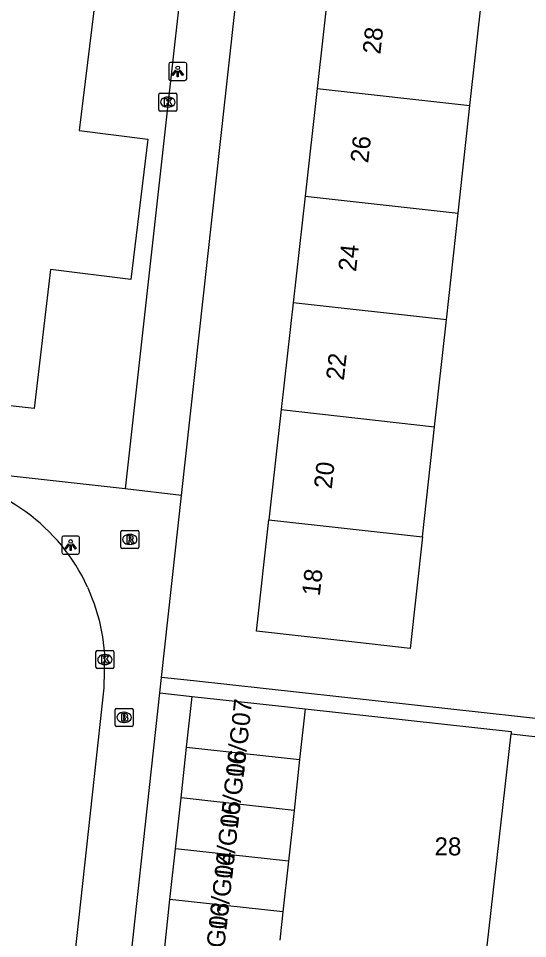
# Model space of a CAD drawing. Extents: x 161928 to 163055, y 386475 to 387428.
# Drawn here: x 162177.9 to 162206.2, y 387064.4 to 387115.4 of the extents above; entities that cross this region are included whole.
import ezdxf

# ---------------------------------------------------------------- set-up
doc = ezdxf.new("R2010")
doc.units = 0
for name, color, linetype in [('IMGEO_Brandkraan', 7, 'Continuous'), ('IMGEO_Groenvoorziening', 7, 'Continuous'), ('IMGEO_Kolk', 7, 'Continuous'), ('IMGEO_Lichtpunt', 7, 'Continuous'), ('IMGEO_Pand', 7, 'Continuous'), ('IMGEO_Pand_nummerreeks', 7, 'Continuous'), ('IMGEO_Rijbaan_lokaal_open', 7, 'Continuous'), ('IMGEO_Rioolput', 7, 'Continuous'), ('IMGEO_Voetpad_open', 7, 'Continuous')]:
    doc.layers.add(name, color=color, linetype=linetype)

msp = doc.modelspace()

# ---------------------------------------------------------------- linework, layer by layer
at = {"layer": 'IMGEO_Brandkraan'}
for p, q in [((162183.308, 387076.214), (162183.308, 387077.066)), ((162183.383, 387077.14), (162184.235, 387077.14)), ((162183.796, 387076.92), (162183.821, 387076.92)), ((162184.309, 387077.066), (162184.309, 387076.214)), ((162183.819, 387076.36), (162183.794, 387076.36)), ((162184.235, 387076.14), (162183.383, 387076.14))]:
    msp.add_line(p, q, dxfattribs=at)
for points in [[(162183.308, 387076.214), (162183.308, 387077.066)], [(162183.383, 387077.14), (162184.235, 387077.14)], [(162183.656, 387076.84), (162183.656, 387076.44), (162183.869, 387076.44)], [(162183.887, 387076.84), (162183.656, 387076.84)], [(162183.835, 387076.759), (162183.781, 387076.759), (162183.781, 387076.683)], [(162184.309, 387077.066), (162184.309, 387076.214)], [(162183.781, 387076.683), (162183.834, 387076.683)], [(162183.843, 387076.607), (162183.781, 387076.607), (162183.781, 387076.526)], [(162183.781, 387076.526), (162183.843, 387076.526)], [(162184.235, 387076.14), (162183.383, 387076.14)]]:
    msp.add_lwpolyline(points, dxfattribs=at)
for centre, radius, start, end in [((162183.385, 387077.064), 0.0765, 91.552, 178.448), ((162183.385, 387077.064), 0.0765, 91.552, 178.448), ((162183.836, 387076.721), 0.0379, 267.8285, 90.9355), ((162183.891, 387076.695), 0.145, 59.4692, 91.5367), ((162183.916, 387076.742), 0.0922, 285.5137, 58.1501), ((162184.233, 387077.064), 0.0765, 1.552, 88.448), ((162184.233, 387077.064), 0.0765, 1.552, 88.448), ((162183.844, 387076.566), 0.0404, 269.8759, 90.5077), ((162183.875, 387076.691), 0.251, 268.6676, 293.5347), ((162183.921, 387076.55), 0.105, 301.3115, 78.989), ((162183.385, 387076.216), 0.0765, 181.552, 268.448), ((162183.385, 387076.216), 0.0765, 181.552, 268.448), ((162184.233, 387076.216), 0.0765, 271.552, 358.448), ((162184.233, 387076.216), 0.0765, 271.552, 358.448)]:
    msp.add_arc(centre, radius, start, end, dxfattribs=at)
for centre, major_axis, ratio, start_param, end_param in [((162183.795, 387076.64), (-0.387, 0.002), 0.722429, 4.712389, 7.853982), ((162183.82, 387076.64), (-0.39, 0.002), 0.717154, 1.570796, 4.712389)]:
    msp.add_ellipse(centre, major_axis=major_axis, ratio=ratio, start_param=start_param, end_param=end_param, dxfattribs=at)
at = {"layer": 'IMGEO_Groenvoorziening'}
msp.add_lwpolyline([(162154.203, 387127.848), (162155.402, 387137.861), (162174.608, 387135.503), (162173.926, 387129.945), (162180.477, 387129.142), (162179.565, 387121.698), (162182.791, 387121.303), (162181.309, 387109.194), (162185.131, 387108.727), (162184.179, 387100.935), (162179.719, 387101.481), (162178.823, 387093.771), (162172.783, 387094.444)], dxfattribs=at)
at = {"layer": 'IMGEO_Kolk'}
for p, q in [((162185.734, 387110.349), (162185.734, 387111.201)), ((162185.809, 387111.275), (162186.661, 387111.275)), ((162186.222, 387111.055), (162186.247, 387111.055)), ((162186.735, 387111.201), (162186.735, 387110.349)), ((162186.245, 387110.495), (162186.22, 387110.495)), ((162186.661, 387110.275), (162185.809, 387110.275)), ((162182.318, 387080.346), (162183.17, 387080.346)), ((162182.243, 387079.42), (162182.243, 387080.272)), ((162182.731, 387080.126), (162182.756, 387080.126)), ((162183.244, 387080.272), (162183.244, 387079.42)), ((162183.17, 387079.346), (162182.318, 387079.346)), ((162182.754, 387079.566), (162182.729, 387079.566))]:
    msp.add_line(p, q, dxfattribs=at)
for points in [[(162185.734, 387110.349), (162185.734, 387111.201)], [(162185.809, 387111.275), (162186.661, 387111.275)], [(162186.055, 387110.975), (162186.178, 387110.975), (162186.178, 387110.824), (162186.308, 387110.975), (162186.472, 387110.975), (162186.326, 387110.824), (162186.479, 387110.575), (162186.327, 387110.575), (162186.242, 387110.739), (162186.178, 387110.672), (162186.178, 387110.575), (162186.055, 387110.575), (162186.055, 387110.975)], [(162186.735, 387111.201), (162186.735, 387110.349)], [(162186.661, 387110.275), (162185.809, 387110.275)], [(162182.318, 387080.346), (162183.17, 387080.346)], [(162182.243, 387079.42), (162182.243, 387080.272)], [(162182.564, 387080.046), (162182.687, 387080.046), (162182.687, 387079.895), (162182.817, 387080.046), (162182.981, 387080.046), (162182.835, 387079.895), (162182.988, 387079.646), (162182.836, 387079.646), (162182.751, 387079.81), (162182.687, 387079.743), (162182.687, 387079.646), (162182.564, 387079.646), (162182.564, 387080.046)], [(162183.244, 387080.272), (162183.244, 387079.42)], [(162183.17, 387079.346), (162182.318, 387079.346)]]:
    msp.add_lwpolyline(points, dxfattribs=at)
for centre, start, end in [((162185.811, 387111.199), 91.552, 178.448), ((162185.811, 387111.199), 91.552, 178.448), ((162186.659, 387111.199), 1.552, 88.448), ((162186.659, 387111.199), 1.552, 88.448), ((162185.811, 387110.351), 181.552, 268.448), ((162185.811, 387110.351), 181.552, 268.448), ((162186.659, 387110.351), 271.552, 358.448), ((162186.659, 387110.351), 271.552, 358.448), ((162182.32, 387080.27), 91.552, 178.448), ((162182.32, 387080.27), 91.552, 178.448), ((162183.168, 387080.27), 1.552, 88.448), ((162183.168, 387080.27), 1.552, 88.448), ((162182.32, 387079.422), 181.552, 268.448), ((162182.32, 387079.422), 181.552, 268.448), ((162183.168, 387079.422), 271.552, 358.448), ((162183.168, 387079.422), 271.552, 358.448)]:
    msp.add_arc(centre, 0.0765, start, end, dxfattribs=at)
for centre, major_axis, ratio, start_param, end_param in [((162186.221, 387110.775), (-0.387, 0.002), 0.722429, 4.712389, 7.853982), ((162186.246, 387110.775), (-0.39, 0.002), 0.717154, 1.570796, 4.712389), ((162182.73, 387079.846), (-0.387, 0.002), 0.722429, 4.712389, 7.853982), ((162182.755, 387079.846), (-0.39, 0.002), 0.717154, 1.570796, 4.712389)]:
    msp.add_ellipse(centre, major_axis=major_axis, ratio=ratio, start_param=start_param, end_param=end_param, dxfattribs=at)
at = {"layer": 'IMGEO_Lichtpunt'}
for p, q in [((162186.286, 387112.881), (162186.286, 387112.074)), ((162186.286, 387112.881), (162186.286, 387112.074)), ((162187.188, 387112.976), (162186.38, 387112.976)), ((162187.188, 387112.976), (162186.38, 387112.976)), ((162187.282, 387112.074), (162187.282, 387112.881)), ((162187.282, 387112.074), (162187.282, 387112.881)), ((162186.38, 387111.98), (162187.188, 387111.98)), ((162186.38, 387111.98), (162187.188, 387111.98)), ((162180.342, 387086.604), (162180.342, 387085.797)), ((162180.342, 387086.604), (162180.342, 387085.797)), ((162181.244, 387086.699), (162180.436, 387086.699)), ((162181.244, 387086.699), (162180.436, 387086.699)), ((162181.338, 387085.797), (162181.338, 387086.604)), ((162181.338, 387085.797), (162181.338, 387086.604)), ((162180.436, 387085.703), (162181.244, 387085.703)), ((162180.436, 387085.703), (162181.244, 387085.703))]:
    msp.add_line(p, q, dxfattribs=at)
for points in [[(162186.66, 387112.545), (162186.699, 387112.517), (162186.511, 387112.255), (162186.473, 387112.282), (162186.66, 387112.545)], [(162186.762, 387112.497), (162186.809, 387112.497), (162186.809, 387112.175), (162186.762, 387112.175), (162186.762, 387112.497)], [(162186.872, 387112.517), (162186.91, 387112.544), (162187.097, 387112.282), (162187.058, 387112.254), (162186.872, 387112.517)], [(162180.716, 387086.268), (162180.755, 387086.24), (162180.567, 387085.978), (162180.529, 387086.005), (162180.716, 387086.268)], [(162180.818, 387086.22), (162180.865, 387086.22), (162180.865, 387085.898), (162180.818, 387085.898), (162180.818, 387086.22)], [(162180.928, 387086.24), (162180.966, 387086.267), (162181.153, 387086.005), (162181.114, 387085.977), (162180.928, 387086.24)]]:
    msp.add_lwpolyline(points, dxfattribs=at)
for centre in [(162186.785, 387112.679), (162180.841, 387086.402)]:
    msp.add_circle(centre, 0.0994, dxfattribs=at)
for centre, start, end in [((162186.38, 387112.881), 90, 180), ((162186.38, 387112.881), 90, 180), ((162187.188, 387112.881), 0, 90), ((162187.188, 387112.881), 0, 90), ((162186.38, 387112.074), 180, 270), ((162186.38, 387112.074), 180, 270), ((162187.188, 387112.074), 270, 0), ((162187.188, 387112.074), 270, 360), ((162180.436, 387086.604), 90, 180), ((162180.436, 387086.604), 90, 180), ((162181.244, 387086.604), 0, 90), ((162181.244, 387086.604), 0, 90), ((162180.436, 387085.797), 180, 270), ((162180.436, 387085.797), 180, 270), ((162181.244, 387085.797), 270, 0), ((162181.244, 387085.797), 270, 360)]:
    msp.add_arc(centre, 0.0946, start, end, dxfattribs=at)
at = {"layer": 'IMGEO_Pand'}
for points in [[(162195.208, 387117.671), (162194.522, 387111.539)], [(162203.008, 387110.59), (162203.682, 387116.723)], [(162194.522, 387111.539), (162193.854, 387105.566)], [(162194.522, 387111.539), (162203.008, 387110.59)], [(162202.351, 387104.616), (162203.008, 387110.59)], [(162193.854, 387105.566), (162193.192, 387099.644)], [(162193.854, 387105.566), (162202.351, 387104.616)], [(162201.7, 387098.693), (162202.351, 387104.616)], [(162193.192, 387099.644), (162192.528, 387093.715)], [(162201.7, 387098.693), (162193.192, 387099.644)], [(162201.048, 387092.762), (162201.7, 387098.693)], [(162192.528, 387093.715), (162191.845, 387087.607)], [(162192.528, 387093.715), (162201.048, 387092.762)], [(162200.376, 387086.653), (162201.048, 387092.762)], [(162200.376, 387086.653), (162199.696, 387080.467), (162196.122, 387080.867), (162191.153, 387081.423), (162191.845, 387087.607)], [(162191.845, 387087.607), (162200.376, 387086.653)], [(162187.275, 387074.986), (162187.583, 387077.806)], [(162187.583, 387077.806), (162192.553, 387077.257), (162193.855, 387077.113)], [(162193.855, 387077.113), (162193.548, 387074.301)], [(162193.855, 387077.113), (162205.301, 387075.849), (162205.287, 387075.728)], [(162203.848, 387062.981), (162205.287, 387075.728)], [(162186.967, 387072.167), (162187.275, 387074.986)], [(162187.275, 387074.986), (162193.548, 387074.301)], [(162193.548, 387074.301), (162193.24, 387071.481)], [(162186.659, 387069.347), (162186.967, 387072.167)], [(162193.24, 387071.481), (162186.967, 387072.167)], [(162193.24, 387071.481), (162192.932, 387068.662)], [(162186.351, 387066.527), (162186.659, 387069.347)], [(162192.932, 387068.662), (162186.659, 387069.347)], [(162192.932, 387068.662), (162192.624, 387065.842)], [(162186.043, 387063.707), (162186.351, 387066.527)], [(162192.624, 387065.842), (162186.351, 387066.527)], [(162192.624, 387065.842), (162192.452, 387064.271)]]:
    msp.add_lwpolyline(points, dxfattribs=at)
at = {"layer": 'IMGEO_Rijbaan_lokaal_open'}
msp.add_lwpolyline([(162181.783, 387083.862), (162181.799, 387083.827), (162182.152, 387082.946), (162182.426, 387082.038), (162182.617, 387081.108), (162182.724, 387080.165), (162182.686, 387078.275), (162180.528, 387058.594)], dxfattribs=at)
msp.add_arc((162172.122, 387079.425), 10.631, 24.6674, 83.564, dxfattribs=at)
at = {"layer": 'IMGEO_Rioolput'}
for p, q in [((162183.694, 387087.011), (162184.546, 387087.011)), ((162183.619, 387086.085), (162183.619, 387086.937)), ((162184.107, 387086.791), (162184.132, 387086.791)), ((162184.62, 387086.937), (162184.62, 387086.085)), ((162184.546, 387086.011), (162183.694, 387086.011)), ((162184.13, 387086.231), (162184.105, 387086.231))]:
    msp.add_line(p, q, dxfattribs=at)
for points in [[(162183.694, 387087.011), (162184.546, 387087.011)], [(162183.619, 387086.085), (162183.619, 387086.937)], [(162184.208, 387086.709), (162183.956, 387086.711), (162183.956, 387086.311)], [(162183.956, 387086.311), (162184.08, 387086.311), (162184.08, 387086.473), (162184.091, 387086.473)], [(162184.134, 387086.63), (162184.08, 387086.63), (162184.08, 387086.549)], [(162184.08, 387086.549), (162184.132, 387086.549)], [(162184.62, 387086.937), (162184.62, 387086.085)], [(162184.546, 387086.011), (162183.694, 387086.011)], [(162184.138, 387086.444), (162184.209, 387086.311), (162184.349, 387086.311), (162184.284, 387086.437)]]:
    msp.add_lwpolyline(points, dxfattribs=at)
for centre, radius, start, end in [((162183.696, 387086.935), 0.0765, 91.552, 178.448), ((162183.696, 387086.935), 0.0765, 91.552, 178.448), ((162184.544, 387086.935), 0.0765, 1.552, 88.448), ((162184.544, 387086.935), 0.0765, 1.552, 88.448), ((162184.09, 387086.42), 0.0533, 26.0293, 88.6989), ((162184.116, 387086.738), 0.19, 274.7715, 282.9687), ((162184.14, 387086.534), 0.0964, 77.0061, 93.1865), ((162184.154, 387086.591), 0.0378, 276.6634, 79.6772), ((162184.207, 387086.599), 0.109, 350.3612, 89.416), ((162184.205, 387086.599), 0.112, 277.5842, 350.9817), ((162184.189, 387086.384), 0.108, 29.5134, 73.7905), ((162183.696, 387086.087), 0.0765, 181.552, 268.448), ((162183.696, 387086.087), 0.0765, 181.552, 268.448), ((162184.544, 387086.087), 0.0765, 271.552, 358.448), ((162184.544, 387086.087), 0.0765, 271.552, 358.448)]:
    msp.add_arc(centre, radius, start, end, dxfattribs=at)
for centre, major_axis, ratio, start_param, end_param in [((162184.106, 387086.511), (-0.387, 0.002), 0.722429, 4.712389, 7.853982), ((162184.131, 387086.511), (-0.39, 0.002), 0.717154, 1.570796, 4.712389)]:
    msp.add_ellipse(centre, major_axis=major_axis, ratio=ratio, start_param=start_param, end_param=end_param, dxfattribs=at)
at = {"layer": 'IMGEO_Voetpad_open'}
for points in [[(162189.473, 387139.756), (162183.859, 387089.312)], [(162187, 387088.946), (162192.319, 387137.306)], [(162183.859, 387089.312), (162171.377, 387090.708)], [(162187, 387088.946), (162183.859, 387089.312)], [(162185.891, 387078.86), (162187, 387088.946)], [(162210.383, 387080.802), (162209.856, 387076.225), (162187.665, 387078.665), (162185.891, 387078.86)], [(162185.796, 387078.002), (162185.891, 387078.86)], [(162183.617, 387058.182), (162185.796, 387078.002)], [(162185.796, 387078.002), (162187.583, 387077.806)], [(162205.287, 387075.728), (162210.53, 387075.136)]]:
    msp.add_lwpolyline(points, dxfattribs=at)

# ---------------------------------------------------------------- texts
at = {"layer": 'IMGEO_Pand_nummerreeks'}
for s, rotation, p in [('28', 83.6162, (162198.031, 387113.401)), ('26', 83.6162, (162197.356, 387107.369)), ('24', 83.6162, (162196.681, 387101.34)), ('22', 83.6162, (162196.006, 387095.308)), ('20', 83.6162, (162195.333, 387089.284)), ('18', 83.6162, (162194.668, 387083.345)), ('16/G07', 83.5645, (162190.432, 387073.237)), ('16/G06', 83.5645, (162190.114, 387070.418)), ('16/G05', 83.5645, (162189.796, 387067.599)), ('16/G04', 83.5645, (162189.478, 387064.781)), ('16/G03', 83.5645, (162189.16, 387061.962))]:
    msp.add_text(s, height=1, rotation=rotation, dxfattribs=at).set_placement(p)
msp.add_text('28', height=1, dxfattribs=at).set_placement((162201.043, 387068.981))

doc.saveas('drawing.dxf')
